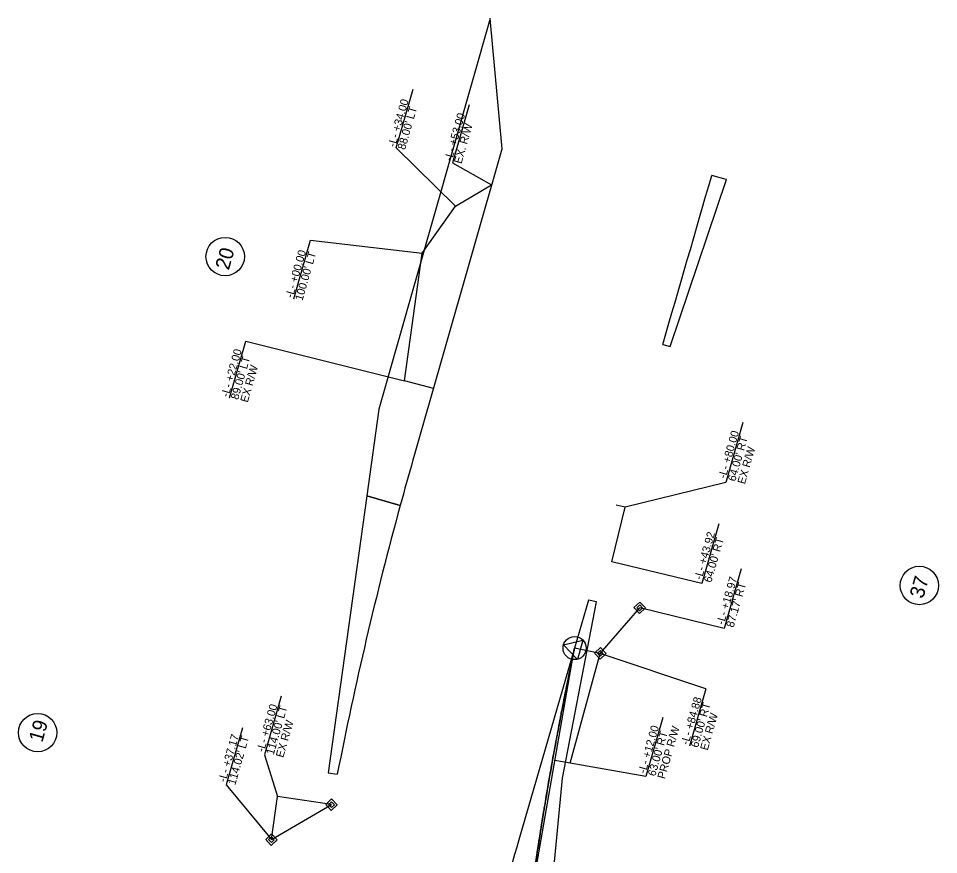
# Model space of a CAD drawing. Extents: x 2097272 to 2098144, y 685104 to 689282.
# Drawn here: x 2097534 to 2098109, y 688760 to 689282 of the extents above; entities that cross this region are included whole.
import ezdxf

# ---------------------------------------------------------------- set-up
doc = ezdxf.new("R2010")
doc.units = 0
for name, color, linetype in [('Prop Easement Construction', 7, 'Continuous'), ('Prop Easement Construction Station Offsets', 7, 'Continuous'), ('Prop Easement Permanent Utility', 7, 'Continuous'), ('Prop Easement Permanent Utility Station Offsets', 7, 'Continuous'), ('Prop Parcel Number CELL', 7, 'Continuous'), ('Prop ROW Marker CELL', 7, 'Continuous'), ('Prop ROW Permanent Easement CELL', 7, 'Continuous'), ('Prop ROW RW Lines', 7, 'Continuous'), ('Prop ROW Station Offsets', 7, 'Continuous'), ('Scratch_Level_3', 7, 'Continuous'), ('Scratch_Level_6', 7, 'Continuous')]:
    doc.layers.add(name, color=color, linetype=linetype)

msp = doc.modelspace()

# ---------------------------------------------------------------- linework, layer by layer
at = {"layer": 'Prop Easement Construction'}
for p, q in [((2097807.07, 689164.84), (2097829.6, 689178.16)), ((2097786.17, 689135.46), (2097807.07, 689164.84)), ((2097775.22, 689055.78), (2097786.17, 689135.46)), ((2097793.2, 689050.98), (2097775.22, 689055.78)), ((2097904.74, 688942.7), (2097912.89, 688976.81)), ((2097912.89, 688976.81), (2097907.32, 688978.19)), ((2097878.54, 688817.14), (2097897.46, 688885.61)), ((2097878.54, 688817.14), (2097869.11, 688818.75)), ((2097692.07, 688769.34), (2097695.94, 688796.18)), ((2097729.57, 688791.16), (2097695.94, 688796.18))]:
    msp.add_line(p, q, dxfattribs=at)
at = {"layer": 'Prop Easement Construction Station Offsets'}
for p, q in [((2097770.04, 689201.24), (2097780.53, 689237.88)), ((2097815.48, 689228.04), (2097805.13, 689191.89)), ((2097770.04, 689201.24), (2097807.07, 689164.84)), ((2097805.13, 689191.89), (2097829.6, 689178.16)), ((2097706, 689107.01), (2097716.49, 689143.64)), ((2097716.49, 689143.64), (2097786.17, 689135.46)), ((2097665.83, 689045.19), (2097675.97, 689080.6)), ((2097675.97, 689080.6), (2097775.22, 689055.78)), ((2097986.52, 689029.71), (2097975.82, 688992.34)), ((2097975.82, 688992.34), (2097912.89, 688976.81)), ((2097971.52, 688966.55), (2097960.82, 688929.18)), ((2097960.82, 688929.18), (2097904.74, 688942.7)), ((2097698.17, 688858.87), (2097687.69, 688822.28)), ((2097936.51, 688845.61), (2097925.95, 688808.73)), ((2097687.69, 688822.28), (2097695.94, 688796.18)), ((2097925.95, 688808.73), (2097878.54, 688817.14))]:
    msp.add_line(p, q, dxfattribs=at)
at = {"layer": 'Prop Easement Permanent Utility'}
for p, q in [((2097897.46, 688885.61), (2097922.06, 688914.07)), ((2097897.46, 688885.61), (2097881.38, 688888.89)), ((2097692.07, 688769.34), (2097729.57, 688791.16))]:
    msp.add_line(p, q, dxfattribs=at)
at = {"layer": 'Prop Easement Permanent Utility Station Offsets'}
for p, q in [((2097985.42, 688938.48), (2097974.72, 688901.11)), ((2097974.72, 688901.11), (2097922.06, 688914.07)), ((2097673.91, 688839.06), (2097663.73, 688803.51)), ((2097663.73, 688803.51), (2097692.07, 688769.34))]:
    msp.add_line(p, q, dxfattribs=at)
at = {"layer": 'Prop Parcel Number CELL'}
for centre in [(2097663.17, 689133.38), (2098096.74, 688928.01), (2097546.03, 688836.14)]:
    msp.add_circle(centre, 12, dxfattribs=at)
at = {"layer": 'Prop ROW Marker CELL'}
for p, q in [((2097922.06, 688914.07), (2097922.06, 688914.07)), ((2097881.38, 688888.89), (2097881.38, 688888.89)), ((2097897.46, 688885.61), (2097897.46, 688885.61)), ((2097729.57, 688791.16), (2097729.57, 688791.16)), ((2097692.07, 688769.34), (2097692.07, 688769.34))]:
    msp.add_line(p, q, dxfattribs=at)
msp.add_lwpolyline([(2097883.12, 688881.89), (2097874.46, 688890.87), (2097886.56, 688893.9)], close=True, dxfattribs=at)
msp.add_circle((2097881.38, 688888.89), 7.2, dxfattribs=at)
at = {"layer": 'Prop ROW Permanent Easement CELL'}
for points in [[(2097918.46, 688914.18), (2097922.16, 688917.67), (2097925.66, 688913.97), (2097921.95, 688910.47)], [(2097920.26, 688914.12), (2097922.11, 688915.87), (2097923.86, 688914.02), (2097922.01, 688912.27)], [(2097893.87, 688885.71), (2097897.57, 688889.21), (2097901.06, 688885.5), (2097897.36, 688882.01)], [(2097895.66, 688885.66), (2097897.52, 688887.41), (2097899.26, 688885.56), (2097897.41, 688883.81)], [(2097725.97, 688791.27), (2097729.67, 688794.76), (2097733.17, 688791.06), (2097729.47, 688787.56)], [(2097727.77, 688791.21), (2097729.62, 688792.96), (2097731.37, 688791.11), (2097729.52, 688789.36)], [(2097688.47, 688769.45), (2097692.18, 688772.94), (2097695.67, 688769.24), (2097691.97, 688765.75)], [(2097690.27, 688769.4), (2097692.13, 688771.14), (2097693.87, 688769.29), (2097692.02, 688767.54)]]:
    msp.add_lwpolyline(points, close=True, dxfattribs=at)
at = {"layer": 'Prop ROW RW Lines'}
msp.add_line((2097854.46, 688734.99), (2097881.38, 688888.89), dxfattribs=at)
at = {"layer": 'Prop ROW Station Offsets'}
for q in [(2097897.46, 688885.61), (2097953.15, 688827.69)]:
    msp.add_line((2097963.41, 688863.55), q, dxfattribs=at)
at = {"layer": 'Scratch_Level_3'}
msp.add_line((2097881.38, 688888.89), (2097846.57, 688769.09), dxfattribs=at)
msp.add_arc((2099533.7, 688278.93), 1756.88, 163.79986, 168.76087, dxfattribs=at)
for points in [[(2097872.03, 688842.59), (2097872.06, 688842.75), (2097872.09, 688842.9), (2097872.15, 688843.22), (2097872.18, 688843.37), (2097872.24, 688843.69), (2097872.27, 688843.84), (2097872.3, 688844.04), (2097872.31, 688844.08), (2097872.33, 688844.16), (2097872.33, 688844.2), (2097872.36, 688844.31), (2097872.37, 688844.39), (2097872.51, 688845.09), (2097872.63, 688845.72), (2097872.99, 688847.59), (2097873.23, 688848.84), (2097873.96, 688852.59), (2097875.43, 688860.08), (2097877.95, 688872.55), (2097880.12, 688882.98), (2097881.28, 688888.42), (2097881.38, 688888.89)], [(2097861.38, 688782.44), (2097861.4, 688782.59), (2097861.43, 688782.75), (2097861.48, 688783.06), (2097861.5, 688783.22), (2097861.56, 688783.54), (2097861.58, 688783.69), (2097861.61, 688783.89), (2097861.62, 688783.93), (2097861.63, 688784.01), (2097861.64, 688784.05), (2097861.66, 688784.17), (2097861.67, 688784.24), (2097861.79, 688784.95), (2097861.89, 688785.58), (2097862.2, 688787.46), (2097862.41, 688788.72), (2097863.04, 688792.48), (2097864.3, 688800.01), (2097866.48, 688812.55), (2097868.74, 688825.08), (2097870.14, 688832.58), (2097870.84, 688836.34), (2097871.08, 688837.59), (2097871.43, 688839.46), (2097871.55, 688840.09), (2097871.68, 688840.79), (2097871.7, 688840.87), (2097871.72, 688840.97), (2097871.72, 688840.99), (2097871.73, 688841.02), (2097871.73, 688841.04), (2097871.74, 688841.1), (2097871.75, 688841.14), (2097871.79, 688841.34), (2097871.82, 688841.49), (2097871.88, 688841.81), (2097871.91, 688841.96), (2097871.97, 688842.28), (2097872, 688842.44), (2097872.03, 688842.59)], [(2097852.36, 688722), (2097852.38, 688722.16), (2097852.4, 688722.32), (2097852.45, 688722.63), (2097852.47, 688722.79), (2097852.51, 688723.1), (2097852.53, 688723.26), (2097852.56, 688723.46), (2097852.56, 688723.5), (2097852.58, 688723.58), (2097852.58, 688723.62), (2097852.6, 688723.74), (2097852.61, 688723.82), (2097852.7, 688724.53), (2097852.79, 688725.16), (2097853.05, 688727.05), (2097853.22, 688728.31), (2097853.75, 688732.09), (2097854.81, 688739.65), (2097856.65, 688752.25), (2097858.57, 688764.83), (2097859.76, 688772.38), (2097860.36, 688776.15), (2097860.56, 688777.41), (2097860.86, 688779.29), (2097860.97, 688779.92), (2097861.08, 688780.63), (2097861.09, 688780.71), (2097861.11, 688780.8), (2097861.11, 688780.82), (2097861.12, 688780.86), (2097861.12, 688780.88), (2097861.13, 688780.94), (2097861.14, 688780.98), (2097861.17, 688781.18), (2097861.2, 688781.33), (2097861.25, 688781.65), (2097861.27, 688781.81), (2097861.32, 688782.12), (2097861.35, 688782.28), (2097861.38, 688782.44)]]:
    msp.add_open_spline(points, degree=3, dxfattribs=at)
at = {"layer": 'Scratch_Level_6'}
for p, q in [((2097828.72, 689282.1), (2097759.22, 689038.11)), ((2097836.07, 689200.75), (2097828.72, 689282.1)), ((2097780.48, 689006.55), (2097836.07, 689200.75)), ((2097976.16, 689181.44), (2097967.08, 689184.05)), ((2097941.14, 689077.25), (2097976.2, 689181.43)), ((2097936.49, 689078.58), (2097941.14, 689077.25)), ((2097759.22, 689038.11), (2097751.67, 688983.94)), ((2097751.67, 688983.94), (2097727.56, 688811.06)), ((2097751.67, 688983.94), (2097772.48, 688977.94)), ((2097772.48, 688977.94), (2097751.67, 688983.94)), ((2097890.07, 688918.8), (2097881.38, 688888.89)), ((2097895.04, 688917.72), (2097890.07, 688918.8)), ((2097873.91, 688807.74), (2097895.04, 688917.72)), ((2097727.56, 688811.06), (2097733.21, 688810.17)), ((2097855.33, 688614.06), (2097873.91, 688807.74))]:
    msp.add_line(p, q, dxfattribs=at)
msp.add_lwpolyline([(2097976.2, 689181.43), (2097976.16, 689181.44)], dxfattribs=at)
for centre, radius, start, end in [((1985922.47, 721619.34), 116644.94, 343.8010979, 343.8550362), ((2100058.96, 688354.32), 2370, 164.02589, 164.74405), ((2100058.96, 688354.32), 2370, 164.74405, 168.91051)]:
    msp.add_arc(centre, radius, start, end, dxfattribs=at)
for points, degree in [([(2097880.82, 688886.27), (2097879.85, 688881.7), (2097877.86, 688872.14), (2097875.43, 688860.08), (2097873.96, 688852.59), (2097873.23, 688848.84), (2097872.99, 688847.59), (2097872.63, 688845.72), (2097872.51, 688845.09), (2097872.37, 688844.39), (2097872.36, 688844.31), (2097872.33, 688844.2), (2097872.33, 688844.16), (2097872.31, 688844.08), (2097872.3, 688844.04), (2097872.29, 688843.95), (2097872.28, 688843.89), (2097872.27, 688843.84)], 3), ([(2097881.29, 688888.46), (2097881.22, 688888.14), (2097881.06, 688887.41), (2097880.91, 688886.68), (2097880.82, 688886.27)], 3), ([(2097881.38, 688888.89), (2097881.35, 688888.74), (2097881.32, 688888.6), (2097881.29, 688888.46)], 2), ([(2097872.22, 688843.62), (2097872.22, 688843.59), (2097872.21, 688843.56), (2097872.18, 688843.37), (2097872.15, 688843.22), (2097872.11, 688843.01), (2097872.1, 688842.96), (2097872.09, 688842.92)], 3), ([(2097872.27, 688843.84), (2097872.25, 688843.77), (2097872.24, 688843.69), (2097872.22, 688843.62)], 2), ([(2097871.67, 688840.74), (2097871.67, 688840.73), (2097871.67, 688840.72), (2097871.55, 688840.09), (2097871.43, 688839.46), (2097871.08, 688837.59), (2097870.84, 688836.34), (2097870.61, 688835.09)], 3), ([(2097871.72, 688840.97), (2097871.72, 688840.96), (2097871.71, 688840.95), (2097871.7, 688840.88), (2097871.69, 688840.81), (2097871.67, 688840.74)], 3), ([(2097871.86, 688841.7), (2097871.85, 688841.69), (2097871.85, 688841.67), (2097871.82, 688841.49), (2097871.79, 688841.34), (2097871.75, 688841.14), (2097871.74, 688841.1), (2097871.73, 688841.04), (2097871.73, 688841.02), (2097871.72, 688840.99), (2097871.72, 688840.98), (2097871.72, 688840.97)], 3), ([(2097871.72, 688840.97), (2097871.72, 688840.97), (2097871.72, 688840.97), (2097871.72, 688840.97)], 2), ([(2097871.94, 688842.12), (2097871.91, 688841.98), (2097871.88, 688841.84), (2097871.86, 688841.7)], 2), ([(2097872.03, 688842.59), (2097872, 688842.44), (2097871.97, 688842.28), (2097871.94, 688842.12)], 2), ([(2097872.09, 688842.92), (2097872.07, 688842.81), (2097872.05, 688842.7), (2097872.03, 688842.59)], 2), ([(2097870.61, 688835.09), (2097870.61, 688835.09), (2097870.61, 688835.09), (2097870.32, 688833.56), (2097870.03, 688832.04), (2097869.75, 688830.51)], 3), ([(2097869.4, 688828.58), (2097869.33, 688828.25), (2097868.35, 688822.91), (2097866.48, 688812.55), (2097864.65, 688801.99), (2097863.71, 688796.45), (2097863.62, 688795.92)], 3), ([(2097869.75, 688830.51), (2097869.63, 688829.87), (2097869.51, 688829.23), (2097869.4, 688828.58)], 2), ([(2097863.62, 688795.92), (2097863.28, 688793.94), (2097862.95, 688791.95), (2097862.41, 688788.72), (2097862.2, 688787.46), (2097861.89, 688785.58), (2097861.79, 688784.95), (2097861.67, 688784.24), (2097861.66, 688784.17), (2097861.64, 688784.07), (2097861.64, 688784.05), (2097861.64, 688784.03)], 3), ([(2097861.11, 688780.8), (2097861.11, 688780.8), (2097861.11, 688780.79), (2097861.09, 688780.71), (2097861.08, 688780.63), (2097860.98, 688780.01), (2097860.89, 688779.46), (2097860.8, 688778.92)], 3), ([(2097861.13, 688780.9), (2097861.12, 688780.88), (2097861.12, 688780.86), (2097861.11, 688780.83), (2097861.11, 688780.82), (2097861.11, 688780.8)], 3), ([(2097861.2, 688781.35), (2097861.18, 688781.24), (2097861.16, 688781.13), (2097861.14, 688780.98), (2097861.13, 688780.94), (2097861.13, 688780.9)], 3), ([(2097861.38, 688782.44), (2097861.35, 688782.28), (2097861.32, 688782.12), (2097861.27, 688781.81), (2097861.25, 688781.65), (2097861.21, 688781.44), (2097861.21, 688781.4), (2097861.2, 688781.35)], 3), ([(2097861.43, 688782.77), (2097861.41, 688782.66), (2097861.39, 688782.55), (2097861.38, 688782.44)], 2), ([(2097861.58, 688783.69), (2097861.56, 688783.59), (2097861.55, 688783.48), (2097861.5, 688783.22), (2097861.48, 688783.06), (2097861.44, 688782.86), (2097861.44, 688782.82), (2097861.43, 688782.77)], 3), ([(2097861.64, 688784.03), (2097861.63, 688784.01), (2097861.63, 688783.99), (2097861.62, 688783.93), (2097861.61, 688783.89), (2097861.6, 688783.8), (2097861.59, 688783.75), (2097861.58, 688783.69)], 3), ([(2097860.16, 688774.89), (2097859.76, 688772.38), (2097858.57, 688764.83), (2097856.65, 688752.25), (2097854.81, 688739.65), (2097853.75, 688732.09), (2097853.22, 688728.31), (2097853.05, 688727.05), (2097852.79, 688725.16), (2097852.7, 688724.53), (2097852.61, 688723.82), (2097852.6, 688723.74), (2097852.58, 688723.62), (2097852.58, 688723.58), (2097852.56, 688723.5), (2097852.56, 688723.46), (2097852.53, 688723.26), (2097852.51, 688723.1), (2097852.47, 688722.79), (2097852.45, 688722.63), (2097852.42, 688722.42), (2097852.41, 688722.37), (2097852.4, 688722.32)], 3), ([(2097860.7, 688778.26), (2097860.52, 688777.14), (2097860.34, 688776.02), (2097860.16, 688774.89)], 2), ([(2097860.76, 688778.66), (2097860.74, 688778.53), (2097860.72, 688778.4), (2097860.7, 688778.26)], 2), ([(2097860.8, 688778.92), (2097860.79, 688778.83), (2097860.78, 688778.75), (2097860.76, 688778.66)], 2)]:
    msp.add_open_spline(points, degree=degree, dxfattribs=at)

# ---------------------------------------------------------------- texts
at = {"layer": 'Prop Easement Construction Station Offsets'}
for s, p in [('-L- +34.00', (2097769.44, 689201.42)), ("88.00' LT", (2097775.45, 689199.7)), ('-L- +53.00', (2097804.71, 689192.7)), ('EX. R/W', (2097810.72, 689190.98)), ('-L- +00.00', (2097705.4, 689107.18)), ("100.00' LT", (2097711.41, 689105.46)), ('-L- +22.00', (2097665.23, 689045.37)), ("89.00' LT", (2097671.24, 689043.65)), ('EX R/W', (2097677.25, 689041.93)), ('-L- +80.00', (2097975.75, 688994.37)), ("64.00' RT", (2097981.76, 688992.65)), ('EX R/W', (2097987.77, 688990.93)), ('-L- +43.92', (2097960.75, 688931.21)), ("64.00' RT", (2097966.76, 688929.49)), ('-L- +63.00', (2097687.43, 688823.62)), ("114.00' LT", (2097693.43, 688821.9)), ('EX R/W', (2097699.44, 688820.18)), ('-L- +12.00', (2097925.74, 688810.27)), ("63.00' RT", (2097931.75, 688808.55)), ('PROP R/W', (2097937.76, 688806.83))]:
    msp.add_text(s, height=5, rotation=74.02589, dxfattribs=at).set_placement(p)
at = {"layer": 'Prop Easement Permanent Utility Station Offsets'}
for s, p in [('-L- +18.97', (2097974.65, 688903.14)), ("87.17' RT", (2097980.66, 688901.42)), ('-L- +37.17', (2097663.46, 688804.83)), ("114.02' LT", (2097669.47, 688803.11))]:
    msp.add_text(s, height=5, rotation=74.02589, dxfattribs=at).set_placement(p)
at = {"layer": 'Prop Parcel Number CELL'}
for s, p in [('20', (2097665.41, 689124.52)), ('37', (2098099.07, 688919.43)), ('19', (2097548.93, 688829.6))]:
    msp.add_text(s, height=9, rotation=74.02589, dxfattribs=at).set_placement(p)
at = {"layer": 'Prop ROW Station Offsets'}
for s, p in [('-L- +84.88', (2097952.47, 688828.12)), ("69.00' RT", (2097958.48, 688826.4)), ('EX R/W', (2097964.48, 688824.68))]:
    msp.add_text(s, height=5, rotation=74.02589, dxfattribs=at).set_placement(p)

doc.saveas('drawing.dxf')
